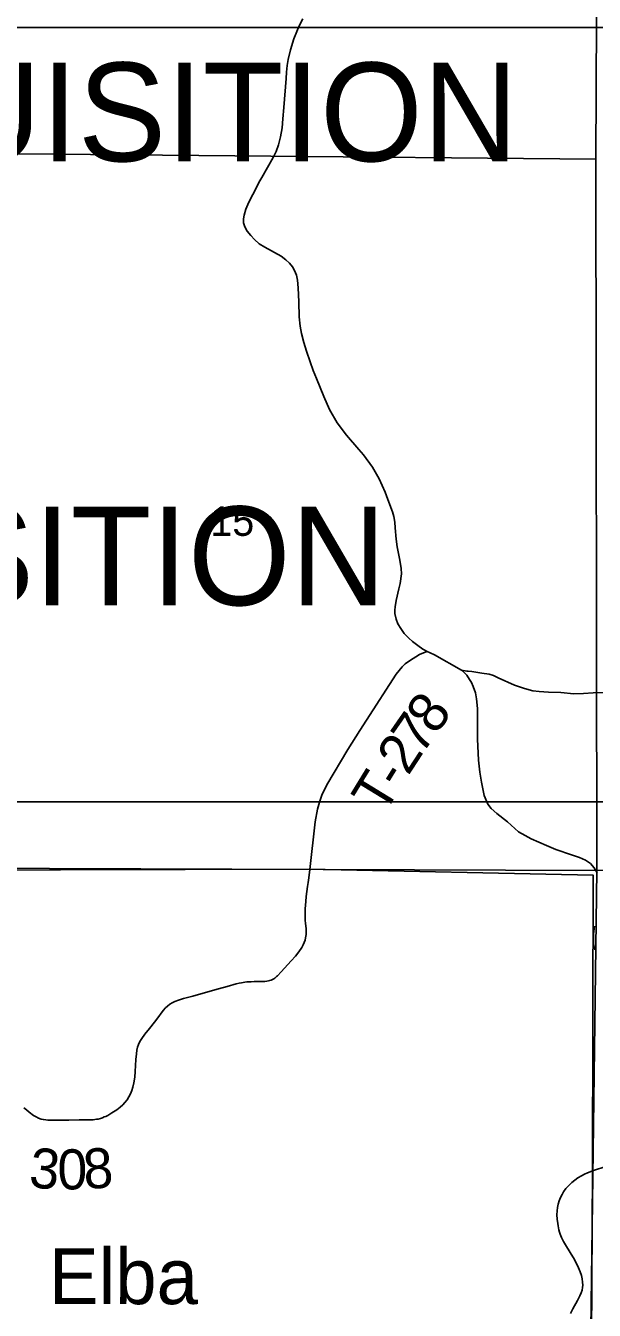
# Model space of a CAD drawing. Extents: x 0 to 34, y 0 to 22.
# Drawn here: x 3.6 to 4.406, y 17.772 to 19.595 of the extents above; entities that cross this region are included whole.
import ezdxf

# ---------------------------------------------------------------- set-up
doc = ezdxf.new("R2010")
doc.units = 0
for name, color, linetype in [('GM_X_Corporation', 7, 'Continuous'), ('GM_X_Section_Text', 7, 'Continuous'), ('GM_X_Township_Road', 7, 'Continuous'), ('GM_X_Township_Road_Text', 7, 'Continuous'), ('GM_X_Township_Text', 7, 'Continuous'), ('GM_X_Unincorporated_Text', 7, 'Continuous'), ('SH_Text', 7, 'Continuous')]:
    doc.layers.add(name, color=color, linetype=linetype)

msp = doc.modelspace()

# ---------------------------------------------------------------- linework, layer by layer
at = {"layer": 'GM_X_Corporation'}
for points in [[(3.3928, 20.4074), (4.4129, 20.4084), (4.4084, 19.4053), (3.384, 19.4149)], [(3.384, 19.4149), (4.4084, 19.4053), (4.4097, 18.3961), (3.3747, 18.3998)], [(4.4097, 18.3961), (5.4623, 18.3997), (5.4343, 17.4017), (4.3969, 17.419)]]:
    msp.add_lwpolyline(points, close=True, dxfattribs=at)
msp.add_lwpolyline([(4.6584, 17.4085), (4.4004, 17.4134), (4.4034, 17.9703), (4.4042, 18.3894), (4.0024, 18.3976), (3.4726, 18.3965), (3.3689, 18.3973), (3.3767, 18.6788), (3.3859, 18.705), (3.3893, 18.721), (3.3872, 18.7823), (3.3779, 18.9241), (3.3711, 18.9531), (3.3709, 19.4088), (3.3147, 19.4093), (2.7824, 19.4152), (2.1, 19.4241), (2.1, 14.1)], dxfattribs=at)
at = {"layer": 'GM_X_Township_Road'}
for points in [[(3.9927, 19.6043), (3.9875, 19.5945), (3.9841, 19.5867), (3.9799, 19.5762), (3.9754, 19.5605), (3.9718, 19.547), (3.9705, 19.5383), (3.9697, 19.529), (3.969, 19.5197), (3.9658, 19.4785), (3.9646, 19.4626), (3.9633, 19.4499), (3.9612, 19.4369), (3.9582, 19.4259), (3.9548, 19.4164), (3.9505, 19.4076), (3.9349, 19.3795), (3.932, 19.3745), (3.9218, 19.3552), (3.9164, 19.3443), (3.9122, 19.3344), (3.9095, 19.3257), (3.9087, 19.3208), (3.9088, 19.315), (3.9105, 19.3092), (3.9138, 19.3031), (3.9193, 19.2969), (3.9243, 19.2912), (3.9311, 19.2854), (3.9388, 19.2807), (3.9622, 19.2675), (3.9689, 19.2626), (3.974, 19.2577), (3.9782, 19.2524), (3.9812, 19.2474), (3.9836, 19.2408), (3.9851, 19.2337), (3.9861, 19.223), (3.9872, 19.2029), (3.9875, 19.1814), (3.989, 19.1684), (3.9908, 19.1582), (3.9942, 19.1454), (3.998, 19.1327), (4.0032, 19.118), (4.0076, 19.1057), (4.012, 19.0942), (4.0224, 19.0687), (4.0304, 19.0501), (4.0414, 19.0313), (4.0549, 19.0138), (4.0724, 18.9932), (4.0786, 18.986), (4.0916, 18.9682), (4.101, 18.9519), (4.1094, 18.933), (4.1135, 18.9223), (4.1199, 18.9051), (4.1218, 18.8981), (4.1231, 18.8901), (4.1235, 18.8821), (4.1251, 18.866), (4.1267, 18.855), (4.1304, 18.8364), (4.1322, 18.8244), (4.1326, 18.8168), (4.1307, 18.8033), (4.129, 18.7957), (4.1252, 18.7793), (4.1238, 18.7702), (4.1234, 18.7653), (4.1233, 18.7605), (4.1252, 18.7526), (4.1275, 18.746), (4.1316, 18.7393), (4.1366, 18.7324), (4.1433, 18.7254), (4.1481, 18.721), (4.1558, 18.7154), (4.163, 18.7102), (4.1689, 18.7067), (4.1732, 18.705), (4.1795, 18.702), (4.2179, 18.6802), (4.2253, 18.6789), (4.2274, 18.6787)], [(4.1689, 18.7067), (4.1638, 18.7049), (4.1584, 18.7022), (4.1438, 18.6936), (4.138, 18.6893), (4.1338, 18.6848), (4.1252, 18.6744), (4.0831, 18.6094), (4.0734, 18.5947), (4.0565, 18.5677), (4.0268, 18.5175), (4.0198, 18.5028), (4.0163, 18.4929), (4.0136, 18.483), (4.0102, 18.4649), (4.0026, 18.3971)], [(4.4103, 18.3925), (4.4058, 18.3998), (4.4007, 18.4056), (4.3934, 18.4105), (4.385, 18.4143), (4.3735, 18.4182), (4.3516, 18.4255), (4.3382, 18.4314), (4.3166, 18.4408), (4.3079, 18.4455), (4.2986, 18.4506), (4.283, 18.4648), (4.2677, 18.4768), (4.26, 18.4839), (4.255, 18.4901), (4.2501, 18.5022), (4.2462, 18.5214), (4.2436, 18.5354), (4.2417, 18.5527), (4.2406, 18.5825), (4.2404, 18.6259), (4.2392, 18.6396), (4.2377, 18.648), (4.2344, 18.6571), (4.2321, 18.6625), (4.2291, 18.6671), (4.2252, 18.6729), (4.2222, 18.6763), (4.2179, 18.6802)], [(4.2274, 18.6787), (4.2326, 18.6781), (4.2466, 18.6761), (4.2568, 18.6747), (4.2631, 18.6724), (4.2696, 18.6693), (4.2929, 18.6589), (4.3069, 18.6542), (4.3188, 18.6511), (4.3278, 18.65), (4.3411, 18.649), (4.3585, 18.6484), (4.3768, 18.6468), (4.3907, 18.647), (4.4042, 18.6479), (4.4196, 18.6486)], [(3.5973, 18.0593), (3.6011, 18.0561), (3.6048, 18.053), (3.6109, 18.0484), (3.6146, 18.0461), (3.6179, 18.0446), (3.622, 18.0432), (3.625, 18.0424), (3.6282, 18.0419), (3.6311, 18.0417), (3.6372, 18.0414), (3.6503, 18.0417), (3.6608, 18.0418), (3.6757, 18.0421), (3.6857, 18.0421), (3.6931, 18.0421), (3.6957, 18.0422), (3.6981, 18.0425), (3.7004, 18.0428), (3.7025, 18.0431), (3.7057, 18.044), (3.7088, 18.045), (3.7112, 18.0461), (3.7136, 18.047), (3.7163, 18.0484), (3.7194, 18.0501), (3.7222, 18.0518), (3.7289, 18.0563), (3.7339, 18.06), (3.7376, 18.0634), (3.7406, 18.0665), (3.7437, 18.0704), (3.7463, 18.0746), (3.7486, 18.079), (3.7505, 18.0836), (3.7519, 18.0884), (3.7532, 18.0945), (3.7545, 18.1024), (3.7553, 18.1105), (3.7562, 18.1279), (3.7568, 18.1359), (3.7575, 18.1408), (3.7585, 18.1451), (3.76, 18.1492), (3.7618, 18.1531), (3.7644, 18.1574), (3.7687, 18.1635), (3.7752, 18.1717), (3.7826, 18.1808), (3.7857, 18.1848), (3.795, 18.1971), (3.7982, 18.2009), (3.8009, 18.2035), (3.8043, 18.2062), (3.8075, 18.2082), (3.8114, 18.21), (3.8166, 18.2121), (3.8237, 18.2143), (3.8369, 18.2177), (3.8483, 18.2208), (3.8734, 18.2281), (3.8853, 18.2315), (3.8985, 18.235), (3.9024, 18.2359), (3.9058, 18.2365), (3.9083, 18.237), (3.9107, 18.2373), (3.9132, 18.2377), (3.9157, 18.2379), (3.9194, 18.2381), (3.9237, 18.2383), (3.9362, 18.2385), (3.9391, 18.2386), (3.9417, 18.2389), (3.9439, 18.2392), (3.9459, 18.2398), (3.948, 18.2404), (3.9496, 18.2411), (3.9515, 18.242), (3.9529, 18.2429), (3.9542, 18.244), (3.9556, 18.2453), (3.9569, 18.2466), (3.962, 18.252), (3.9764, 18.2675), (3.9825, 18.2745), (3.987, 18.2804), (3.9912, 18.2866), (3.9934, 18.2903), (3.9949, 18.2937), (3.9962, 18.2972), (3.9968, 18.3002), (3.9972, 18.3025), (3.9974, 18.3049), (3.9975, 18.3068), (3.9975, 18.3098), (3.9974, 18.3129), (3.997, 18.3172), (3.9966, 18.3209), (3.9962, 18.3254), (3.996, 18.33), (3.9959, 18.3357), (3.9961, 18.3413), (3.9969, 18.3517), (3.9976, 18.3591), (3.9995, 18.3733), (4.0003, 18.3788), (4.0012, 18.3855), (4.0026, 18.3971)], [(4.4067, 18.2832), (4.4055, 18.2893), (4.405, 18.2925), (4.4048, 18.2955), (4.4047, 18.2987), (4.4047, 18.3018), (4.405, 18.3057), (4.4054, 18.3095), (4.4057, 18.3132), (4.4061, 18.317)], [(4.4036, 17.9698), (4.4236, 17.9761)], [(4.3723, 17.7671), (4.3758, 17.774), (4.382, 17.7855), (4.3855, 17.7921), (4.3875, 17.7967), (4.3886, 17.8002), (4.3893, 17.8039), (4.3897, 17.8076), (4.3895, 17.8119), (4.3889, 17.8162), (4.3878, 17.8211), (4.3861, 17.8264), (4.3838, 17.8322), (4.3803, 17.8393), (4.3765, 17.8463), (4.3733, 17.8516), (4.3638, 17.8669), (4.3624, 17.8694), (4.3609, 17.8724), (4.3597, 17.875), (4.3586, 17.8775), (4.3577, 17.8799), (4.3567, 17.8828), (4.3559, 17.8859), (4.3552, 17.8888), (4.3546, 17.8916), (4.3541, 17.8949), (4.3533, 17.901), (4.353, 17.9072), (4.3532, 17.9128), (4.3538, 17.9177), (4.3548, 17.9226), (4.3562, 17.9273), (4.3581, 17.9319), (4.3603, 17.9363), (4.3626, 17.94), (4.3659, 17.9444), (4.37, 17.9491), (4.374, 17.953), (4.3783, 17.9566), (4.3829, 17.9598), (4.3877, 17.9626), (4.3923, 17.9649), (4.3965, 17.9668), (4.4, 17.9684), (4.4036, 17.9698)]]:
    msp.add_lwpolyline(points, dxfattribs=at)
at = {"layer": 'GM_X_Township_Text'}
msp.add_lwpolyline([(2.1, 19.4241), (2.7824, 19.4152), (3.3147, 19.4093), (3.3709, 19.4088), (3.3711, 18.9531), (3.3779, 18.9241), (3.3872, 18.7823), (3.3893, 18.721), (3.3859, 18.705), (3.3767, 18.6788), (3.3689, 18.3973), (3.4726, 18.3965), (4.0024, 18.3976), (4.4042, 18.3894), (4.4034, 17.9703), (4.4004, 17.4134), (4.6584, 17.4085)], dxfattribs=at)
at = {"layer": 'SH_Text'}
for points in [[(4.4854, 19.5924), (2.4095, 19.5924), (2.4095, 18.4935), (4.4854, 18.4935)], [(2.4095, 19.5924), (4.4854, 19.5924), (4.4854, 18.4935), (2.4095, 18.4935)]]:
    msp.add_lwpolyline(points, close=True, dxfattribs=at)

# ---------------------------------------------------------------- texts
at = {"layer": 'GM_X_Section_Text'}
msp.add_text('15', height=0.04186, rotation=0, dxfattribs=at).set_placement((3.8616, 18.8708))
at = {"layer": 'GM_X_Township_Road_Text'}
for s, rotation, p in [('8', 53.4465, (4.1807, 18.5868)), ('7', 55.2361, (4.161, 18.5584)), ('2', 56.9046, (4.1421, 18.5294)), ('T', 58.5166, (4.1078, 18.4737)), ('-', 58.0964, (4.13, 18.5099)), ('3', 354.2629, (3.6032, 17.9468)), ('0', 1.047, (3.6454, 17.943)), ('8', 3.7012, (3.6832, 17.9437))]:
    msp.add_text(s, height=0.0568, rotation=rotation, dxfattribs=at).set_placement(p)
at = {"layer": 'GM_X_Unincorporated_Text'}
msp.add_text('Elba', height=0.07898, rotation=0, dxfattribs=at).set_placement((3.6328, 17.7805))
at = {"layer": 'SH_Text'}
for s, p in [('BEGIN ACQUISITION', (2.4465, 19.4024)), ('END ACQUISITION', (2.4465, 18.7724))]:
    msp.add_text(s, height=0.14, dxfattribs=at).set_placement(p)

doc.saveas('drawing.dxf')
